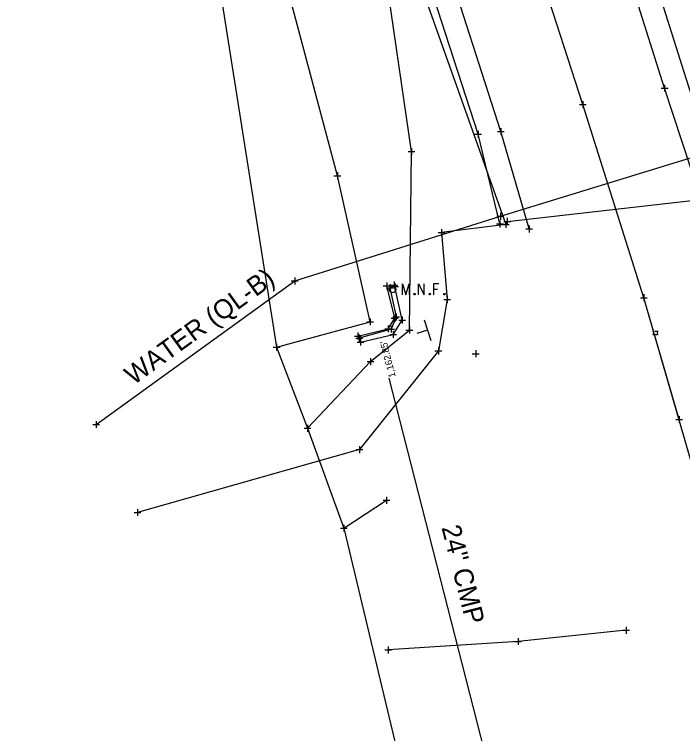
# Model space of a CAD drawing. Extents: x 2324380 to 2325559, y 691096 to 693386.
# Drawn here: x 2324992.2 to 2325090, y 692064.7 to 692170 of the extents above; entities that cross this region are included whole.
import ezdxf

# ---------------------------------------------------------------- set-up
doc = ezdxf.new("R2010")
doc.units = 0
for name, color, linetype in [('DR_X_Headwall', 7, 'Continuous'), ('DR_X_Storm_Sewer', 7, 'Continuous'), ('DR_X_Text', 7, 'Continuous'), ('PM_X_Cells', 7, 'Continuous'), ('PM_X_CL_Double_Solid', 7, 'Continuous'), ('PM_X_Transverse_Line', 7, 'Continuous'), ('PV_X_COP', 7, 'Continuous'), ('PV_X_EOP', 7, 'Continuous'), ('SC_Scratch1', 7, 'Continuous'), ('SN_X_Public', 7, 'Continuous'), ('SV_X_Break_Lines', 7, 'Continuous'), ('SV_X_Control_Cells_Found', 7, 'Continuous'), ('SV_X_Shot_Marker', 7, 'Continuous'), ('SV_X_Terrain_Boundary', 7, 'Continuous'), ('SV_X_Toe_of_Slope', 7, 'Continuous'), ('SV_X_Top_of_Bank', 7, 'Continuous'), ('UT_X_Gas', 7, 'Continuous'), ('UT_X_Water', 7, 'Continuous'), ('UT_X_Water_Text', 7, 'Continuous')]:
    doc.layers.add(name, color=color, linetype=linetype)

msp = doc.modelspace()

# ---------------------------------------------------------------- linework, layer by layer
at = {"layer": 'DR_X_Headwall'}
msp.add_lwpolyline([(2325047.89, 692130.13), (2325047.14, 692129.97), (2325048.07, 692125.69), (2325047.34, 692123.9), (2325042.65, 692122.6), (2325042.85, 692122), (2325047.62, 692123.13), (2325048.94, 692125.24)], close=True, dxfattribs=at)
at = {"layer": 'DR_X_Storm_Sewer'}
msp.add_line((2325065.92, 692043.03), (2325047.03, 692116.72), dxfattribs=at)
at = {"layer": 'PM_X_Cells'}
for p, q in [((2325085.63, 692123.61), (2325085.73, 692123.61)), ((2325085.63, 692123.13), (2325085.73, 692123.13)), ((2325085.79, 692123.61), (2325085.89, 692123.61)), ((2325085.79, 692123.13), (2325085.89, 692123.13)), ((2325085.96, 692123.61), (2325086.06, 692123.61)), ((2325085.96, 692123.13), (2325086.06, 692123.13)), ((2325086.01, 692123.37), (2325086.01, 692123.37)), ((2325086.13, 692123.61), (2325086.23, 692123.61)), ((2325086.13, 692123.13), (2325086.23, 692123.13)), ((2325086.3, 692123.61), (2325086.4, 692123.61)), ((2325086.3, 692123.13), (2325086.4, 692123.13))]:
    msp.add_line(p, q, dxfattribs=at)
for centre, start, end in [((2325085.47, 692123.37), 42.0847, 58.0262), ((2325085.47, 692123.37), 301.9738, 317.9205), ((2325085.47, 692123.37), 18.8878, 34.8207), ((2325085.47, 692123.37), 325.1782, 341.1111), ((2325085.47, 692123.37), 348.3904, 11.6202), ((2325086.55, 692123.37), 168.3816, 191.6091), ((2325086.55, 692123.37), 145.1782, 161.1098), ((2325086.55, 692123.37), 198.8872, 214.8207), ((2325086.55, 692123.37), 121.9738, 137.9163), ((2325086.55, 692123.37), 222.0817, 238.0262)]:
    msp.add_arc(centre, 0.288, start, end, dxfattribs=at)
at = {"layer": 'PM_X_CL_Double_Solid'}
for points in [[(2325089.48, 692110.68), (2325084.32, 692128.51), (2325075.39, 692156.76), (2325066.63, 692183.78), (2325058.11, 692209.28), (2325049.62, 692233.9), (2325041.55, 692256.48), (2325033.1, 692279.67), (2325023.32, 692305.87), (2325013.77, 692329.93)], [(2325065.9, 692078.22), (2325046.89, 692076.97)]]:
    msp.add_lwpolyline(points, dxfattribs=at)
at = {"layer": 'PM_X_Transverse_Line'}
for points in [[(2325119.99, 692049.57), (2325112.24, 692077.64), (2325103.35, 692107.53), (2325096.49, 692131.33), (2325087.35, 692159.17), (2325078.82, 692186.21), (2325070.07, 692212.52), (2325061.8, 692237.43), (2325045.09, 692283.67), (2325035.69, 692308.59), (2325025.65, 692334.45)], [(2325067.54, 692138.56), (2325063.39, 692152.82), (2325054.73, 692179.69), (2325046.66, 692204.76), (2325037.56, 692230.19), (2325029.78, 692252.06), (2325021.19, 692275.25), (2325011.82, 692300.8), (2325001.5, 692326.71)]]:
    msp.add_lwpolyline(points, dxfattribs=at)
at = {"layer": 'PV_X_COP'}
for points in [[(2325108.45, 692046.03), (2325099.34, 692075.66), (2325091, 692105.35), (2325084.32, 692128.51), (2325075.39, 692156.76), (2325066.63, 692183.78), (2325058.11, 692209.28), (2325049.62, 692233.9), (2325041.55, 692256.48), (2325033.1, 692279.67), (2325023.32, 692305.87), (2325013.77, 692329.93)], [(2325081.71, 692079.85), (2325065.9, 692078.22), (2325046.89, 692076.97)]]:
    msp.add_lwpolyline(points, dxfattribs=at)
at = {"layer": 'PV_X_EOP'}
for p, q in [((2325060.05, 692152.41), (2325051.56, 692178.68)), ((2325063.25, 692139.29), (2325060.05, 692152.41)), ((2325040.39, 692094.78), (2325046.64, 692098.87))]:
    msp.add_line(p, q, dxfattribs=at)
msp.add_lwpolyline([(2325123.25, 692051.46), (2325115.82, 692078.51), (2325110.86, 692095.71), (2325106.46, 692109.57), (2325099.73, 692132.13), (2325090.5, 692160.58), (2325082.22, 692186.84), (2325072.77, 692213.83), (2325064.19, 692238.4), (2325059.92, 692251), (2325055.34, 692262.57), (2325047.32, 692284.59), (2325037.78, 692309.71), (2325028.4, 692335.51)], dxfattribs=at)
at = {"layer": 'SN_X_Public'}
for p, q in [((2325052.15, 692125.28), (2325053.12, 692122.23)), ((2325052.63, 692123.76), (2325051.11, 692123.28))]:
    msp.add_line(p, q, dxfattribs=at)
at = {"layer": 'SV_X_Break_Lines'}
msp.add_lwpolyline([(2325042.44, 692122.9), (2325046.88, 692123.94), (2325047.85, 692125.49), (2325046.68, 692130.22), (2325047.78, 692130.36)], dxfattribs=at)
at = {"layer": 'SV_X_Control_Cells_Found'}
for points in [[(2325048.97, 692128.93), (2325048.97, 692130.53), (2325049.48, 692128.93), (2325049.96, 692130.53), (2325049.96, 692128.93)], [(2325051.34, 692128.93), (2325051.34, 692130.53), (2325052.17, 692128.93), (2325052.17, 692130.53)], [(2325054.32, 692130.53), (2325053.55, 692130.53), (2325053.55, 692128.93)], [(2325053.55, 692129.74), (2325054.1, 692129.74)], [(2325050.73, 692129.14), (2325050.79, 692129.14), (2325050.82, 692129.11), (2325050.85, 692129.06), (2325050.85, 692129), (2325050.82, 692128.95), (2325050.79, 692128.93), (2325050.73, 692128.93), (2325050.7, 692128.95), (2325050.67, 692129), (2325050.67, 692129.06), (2325050.7, 692129.11), (2325050.73, 692129.14)], [(2325052.95, 692129.14), (2325053, 692129.14), (2325053.04, 692129.11), (2325053.07, 692129.06), (2325053.07, 692129), (2325053.04, 692128.95), (2325053, 692128.93), (2325052.95, 692128.93), (2325052.92, 692128.95), (2325052.88, 692129), (2325052.88, 692129.06), (2325052.92, 692129.11), (2325052.95, 692129.14)], [(2325055.1, 692129.14), (2325055.15, 692129.14), (2325055.19, 692129.11), (2325055.22, 692129.06), (2325055.22, 692129), (2325055.19, 692128.95), (2325055.15, 692128.93), (2325055.1, 692128.93), (2325055.06, 692128.95), (2325055.03, 692129), (2325055.03, 692129.06), (2325055.06, 692129.11), (2325055.1, 692129.14)]]:
    msp.add_lwpolyline(points, dxfattribs=at)
msp.add_circle((2325047.53, 692129.73), 0.497, dxfattribs=at)
at = {"layer": 'SV_X_Shot_Marker'}
for p, q in [((2325086.85, 692159.17), (2325087.85, 692159.17)), ((2325087.35, 692159.67), (2325087.35, 692158.67)), ((2325087.35, 692159.17), (2325087.35, 692159.17)), ((2325074.89, 692156.76), (2325075.89, 692156.76)), ((2325074.89, 692156.76), (2325075.89, 692156.76)), ((2325075.39, 692157.26), (2325075.39, 692156.26)), ((2325075.39, 692157.26), (2325075.39, 692156.26)), ((2325075.39, 692156.76), (2325075.39, 692156.76)), ((2325075.39, 692156.76), (2325075.39, 692156.76)), ((2325060.05, 692152.91), (2325060.05, 692151.91)), ((2325062.89, 692152.82), (2325063.89, 692152.82)), ((2325063.39, 692153.32), (2325063.39, 692152.32)), ((2325063.39, 692152.82), (2325063.39, 692152.82)), ((2325059.55, 692152.41), (2325060.55, 692152.41)), ((2325060.05, 692152.41), (2325060.05, 692152.41)), ((2325050.31, 692150.39), (2325050.31, 692149.39)), ((2325049.81, 692149.89), (2325050.81, 692149.89)), ((2325050.31, 692149.89), (2325050.31, 692149.89)), ((2325038.96, 692146.35), (2325039.96, 692146.35)), ((2325039.46, 692146.85), (2325039.46, 692145.85)), ((2325039.46, 692146.35), (2325039.46, 692146.35)), ((2325063.32, 692140.91), (2325063.32, 692139.91)), ((2325062.82, 692140.41), (2325063.82, 692140.41)), ((2325063.32, 692140.41), (2325063.32, 692140.41)), ((2325064.33, 692140.17), (2325064.33, 692139.17)), ((2325062.75, 692139.29), (2325063.75, 692139.29)), ((2325063.25, 692139.79), (2325063.25, 692138.79)), ((2325063.25, 692139.29), (2325063.25, 692139.29)), ((2325063.62, 692139.21), (2325064.62, 692139.21)), ((2325063.83, 692139.67), (2325064.83, 692139.67)), ((2325064.12, 692139.71), (2325064.12, 692138.71)), ((2325064.12, 692139.21), (2325064.12, 692139.21)), ((2325064.33, 692139.67), (2325064.33, 692139.67)), ((2325067.54, 692139.06), (2325067.54, 692138.06)), ((2325054.22, 692138.03), (2325055.22, 692138.03)), ((2325054.72, 692138.53), (2325054.72, 692137.53)), ((2325054.72, 692138.03), (2325054.72, 692138.03)), ((2325067.04, 692138.56), (2325068.04, 692138.56)), ((2325067.54, 692138.56), (2325067.54, 692138.56)), ((2325033.21, 692131.46), (2325033.21, 692130.46)), ((2325032.71, 692130.96), (2325033.71, 692130.96)), ((2325033.21, 692130.96), (2325033.21, 692130.96)), ((2325046.68, 692130.72), (2325046.68, 692129.72)), ((2325047.14, 692130.47), (2325047.14, 692129.47)), ((2325047.78, 692130.86), (2325047.78, 692129.86)), ((2325047.89, 692130.63), (2325047.89, 692129.63)), ((2325046.18, 692130.22), (2325047.18, 692130.22)), ((2325046.64, 692129.97), (2325047.64, 692129.97)), ((2325046.68, 692130.22), (2325046.68, 692130.22)), ((2325047.14, 692129.97), (2325047.14, 692129.97)), ((2325047.28, 692130.36), (2325048.28, 692130.36)), ((2325047.39, 692130.13), (2325048.39, 692130.13)), ((2325047.78, 692130.36), (2325047.78, 692130.36)), ((2325047.89, 692130.13), (2325047.89, 692130.13)), ((2325055.52, 692128.76), (2325055.52, 692127.76)), ((2325083.82, 692128.51), (2325084.82, 692128.51)), ((2325083.82, 692128.51), (2325084.82, 692128.51)), ((2325084.32, 692129.01), (2325084.32, 692128.01)), ((2325084.32, 692129.01), (2325084.32, 692128.01)), ((2325084.32, 692128.51), (2325084.32, 692128.51)), ((2325084.32, 692128.51), (2325084.32, 692128.51)), ((2325055.02, 692128.26), (2325056.02, 692128.26)), ((2325055.52, 692128.26), (2325055.52, 692128.26)), ((2325048.07, 692126.19), (2325048.07, 692125.19)), ((2325044.25, 692125.48), (2325044.25, 692124.48)), ((2325047.35, 692125.49), (2325048.35, 692125.49)), ((2325047.57, 692125.69), (2325048.57, 692125.69)), ((2325047.85, 692125.99), (2325047.85, 692124.99)), ((2325047.85, 692125.49), (2325047.85, 692125.49)), ((2325048.07, 692125.69), (2325048.07, 692125.69)), ((2325048.44, 692125.24), (2325049.44, 692125.24)), ((2325048.94, 692125.74), (2325048.94, 692124.74)), ((2325048.94, 692125.24), (2325048.94, 692125.24)), ((2325043.75, 692124.98), (2325044.75, 692124.98)), ((2325044.25, 692124.98), (2325044.25, 692124.98)), ((2325046.88, 692124.44), (2325046.88, 692123.44)), ((2325047.34, 692124.4), (2325047.34, 692123.4)), ((2325050, 692124.28), (2325050, 692123.28)), ((2325042.44, 692123.4), (2325042.44, 692122.4)), ((2325042.65, 692123.1), (2325042.65, 692122.1)), ((2325046.38, 692123.94), (2325047.38, 692123.94)), ((2325046.84, 692123.9), (2325047.84, 692123.9)), ((2325046.88, 692123.94), (2325046.88, 692123.94)), ((2325047.12, 692123.13), (2325048.12, 692123.13)), ((2325047.34, 692123.9), (2325047.34, 692123.9)), ((2325047.62, 692123.63), (2325047.62, 692122.63)), ((2325047.62, 692123.13), (2325047.62, 692123.13)), ((2325049.5, 692123.78), (2325050.5, 692123.78)), ((2325050, 692123.78), (2325050, 692123.78)), ((2325041.94, 692122.9), (2325042.94, 692122.9)), ((2325042.15, 692122.6), (2325043.15, 692122.6)), ((2325042.35, 692122), (2325043.35, 692122)), ((2325042.44, 692122.9), (2325042.44, 692122.9)), ((2325042.65, 692122.6), (2325042.65, 692122.6)), ((2325042.85, 692122.5), (2325042.85, 692121.5)), ((2325042.85, 692122), (2325042.85, 692122)), ((2325030.06, 692121.28), (2325031.06, 692121.28)), ((2325030.56, 692121.78), (2325030.56, 692120.78)), ((2325030.56, 692121.28), (2325030.56, 692121.28)), ((2325054.24, 692121.22), (2325054.24, 692120.22)), ((2325053.74, 692120.72), (2325054.74, 692120.72)), ((2325054.24, 692120.72), (2325054.24, 692120.72)), ((2325059.21, 692120.31), (2325060.21, 692120.31)), ((2325059.71, 692120.81), (2325059.71, 692119.81)), ((2325059.71, 692120.31), (2325059.71, 692120.31)), ((2325043.8, 692119.16), (2325044.8, 692119.16)), ((2325044.3, 692119.66), (2325044.3, 692118.66)), ((2325044.3, 692119.16), (2325044.3, 692119.16)), ((2325004.14, 692110.45), (2325004.14, 692109.45)), ((2325088.98, 692110.68), (2325089.98, 692110.68)), ((2325089.48, 692111.18), (2325089.48, 692110.18)), ((2325089.48, 692110.68), (2325089.48, 692110.68)), ((2325003.64, 692109.95), (2325004.64, 692109.95)), ((2325004.14, 692109.95), (2325004.14, 692109.95)), ((2325034.58, 692109.4), (2325035.58, 692109.4)), ((2325035.08, 692109.9), (2325035.08, 692108.9)), ((2325035.08, 692109.4), (2325035.08, 692109.4)), ((2325042.19, 692106.28), (2325043.19, 692106.28)), ((2325042.69, 692106.78), (2325042.69, 692105.78)), ((2325042.69, 692106.28), (2325042.69, 692106.28)), ((2325046.14, 692098.87), (2325047.14, 692098.87)), ((2325046.64, 692099.37), (2325046.64, 692098.37)), ((2325046.64, 692098.87), (2325046.64, 692098.87)), ((2325009.71, 692097.08), (2325010.71, 692097.08)), ((2325010.21, 692097.58), (2325010.21, 692096.58)), ((2325010.21, 692097.08), (2325010.21, 692097.08)), ((2325039.89, 692094.78), (2325040.89, 692094.78)), ((2325040.39, 692095.28), (2325040.39, 692094.28)), ((2325040.39, 692094.78), (2325040.39, 692094.78)), ((2325081.71, 692080.35), (2325081.71, 692079.35)), ((2325081.21, 692079.85), (2325082.21, 692079.85)), ((2325081.71, 692079.85), (2325081.71, 692079.85)), ((2325065.4, 692078.22), (2325066.4, 692078.22)), ((2325065.4, 692078.22), (2325066.4, 692078.22)), ((2325065.9, 692078.72), (2325065.9, 692077.72)), ((2325065.9, 692078.72), (2325065.9, 692077.72)), ((2325065.9, 692078.22), (2325065.9, 692078.22)), ((2325065.9, 692078.22), (2325065.9, 692078.22)), ((2325046.39, 692076.97), (2325047.39, 692076.97)), ((2325046.39, 692076.97), (2325047.39, 692076.97)), ((2325046.89, 692077.47), (2325046.89, 692076.47)), ((2325046.89, 692077.47), (2325046.89, 692076.47)), ((2325046.89, 692076.97), (2325046.89, 692076.97)), ((2325046.89, 692076.97), (2325046.89, 692076.97))]:
    msp.add_line(p, q, dxfattribs=at)
at = {"layer": 'SV_X_Terrain_Boundary'}
msp.add_lwpolyline([(2325014.61, 692222.14), (2325030.56, 692121.28), (2325035.08, 692109.4), (2325040.39, 692094.78), (2325055.27, 692032.59)], dxfattribs=at)
at = {"layer": 'SV_X_Toe_of_Slope'}
msp.add_lwpolyline([(2325030.56, 692121.28), (2325044.25, 692124.98), (2325039.46, 692146.35), (2325032.38, 692172.92), (2325024.69, 692196.66), (2325014.61, 692222.14), (2325009.37, 692243.9), (2325000.08, 692267.16), (2324990.82, 692292.96), (2324978.96, 692319.34)], dxfattribs=at)
at = {"layer": 'SV_X_Top_of_Bank'}
msp.add_lwpolyline([(2325035.08, 692109.4), (2325044.3, 692119.16), (2325050, 692123.78), (2325050.31, 692149.89), (2325046.25, 692177.76), (2325037.53, 692201.96), (2325029.65, 692226.14), (2325021.48, 692249.35), (2325013.46, 692271.39), (2325002.03, 692298.08), (2324994.77, 692324.28)], dxfattribs=at)
at = {"layer": 'UT_X_Gas'}
for points in [[(2324898.38, 692544.09), (2324919.05, 692496.67), (2324937.7, 692455), (2324959.41, 692406.62), (2324976.91, 692366.17), (2325000.38, 692311.88), (2325017.09, 692269.4), (2325035.58, 692222.9), (2325041.06, 692204.36), (2325050.14, 692178.45), (2325064.12, 692139.21), (2325054.72, 692138.03), (2325055.52, 692128.26), (2325054.24, 692120.72), (2325042.69, 692106.28), (2325010.21, 692097.08)], [(2325064.33, 692139.67), (2325096.07, 692143.24), (2325113.64, 692144.83), (2325141.06, 692149.71)]]:
    msp.add_lwpolyline(points, dxfattribs=at)
at = {"layer": 'UT_X_Water'}
msp.add_lwpolyline([(2325004.14, 692109.95), (2325033.21, 692130.96), (2325063.32, 692140.41), (2325105.29, 692153.32)], dxfattribs=at)

# ---------------------------------------------------------------- texts
at = {"layer": 'DR_X_Text'}
msp.add_text('24" CMP', height=2.8, rotation=284.3729, dxfattribs=at).set_placement((2325054.68, 692094.89))
at = {"layer": 'SC_Scratch1'}
msp.add_text("1,162.85'", height=1, rotation=104.3729, dxfattribs=at).set_placement((2325048, 692116.97))
at = {"layer": 'UT_X_Water_Text'}
msp.add_text('WATER (QL-B)', height=2.8, rotation=35.8664, dxfattribs=at).set_placement((2325009.62, 692115.64))

doc.saveas('drawing.dxf')
